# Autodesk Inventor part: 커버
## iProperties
Company: 한국ATC센터
Created: 2012-05
Part Number: 커버
Document SubType Name: 모델링
Designer: KYOUNG IL JANG
Mass: 196.659 g
Surface Area: 278.607 cm^2
Volume: 72.5678 cm^3
Density: 2.71 g/cm^3
Material: 알루미늄-6061
변환 표준: STEP AP214IS
파일 이름: C:\Users\SeoGD\Desktop\?쒗뿕\而ㅻ쾭-1.stp
전처리기: Build: 253, Release: 2010 SP1 - Date: Wed 07/29/2009
전송 단위: 밀리미터
불확실성: 0.01
Author: KYOUNG IL JANG
